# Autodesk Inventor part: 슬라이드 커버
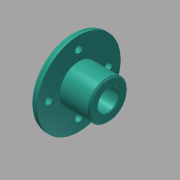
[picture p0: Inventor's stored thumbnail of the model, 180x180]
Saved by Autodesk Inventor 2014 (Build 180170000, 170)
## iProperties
Created: 2015-12
Part Number: 슬라이드 커버
Document SubType Name: Modeling
Designer: mdu
Density: 2.71 g/cm^3
Material: 알루미늄 6061
Mass: 49.5723 g
Surface Area: 80.7135 cm^2
Volume: 18.2924 cm^3
Appearance: 알루미늄 - 평지
Author: mdu
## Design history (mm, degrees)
sketch "스케치1"
  geometry: L1 (-12.5, 0)-(12.5, 0); L2 (-12.5, 0)-(-12.5, 28); L3 (-12.5, 28)-(-7.5, 28); L4 (-7.5, 28)-(-7.5, 13); L5 (-7.5, 13)-(12.5, 13); L6 (12.5, 13)-(12.5, 0); 2 further points
  constraints: 12 end point, 3 perpendicular, 1 coincident, 1 horizontal, 1 midpoint, 1 parallel
  dimensions: "d1" = 56 diameter of L3 L1; "d2" = 26 diameter of L5 L1; "d5" = 5 distance of L2.end L3.end; "d32" = 20 distance of L4.end L5.end
revolve "회전1" sketch "스케치1" stored, may be unused: angle "d6" = 90 deg
sketch "스케치2" dims "d33" = 40
  geometry: 3 further points
  constraints: 2 vertical alignment, 1 coincident, 2 other
hole "구멍1" sketch "스케치2" at (0, 20) diameter "d8" = 5; stored, may be unused: countersink angle "d12" = 90 deg, drill point angle "d14" = 118 deg; dims "d9" = 6, "d10" = 8, "d11" = 4.4, "d13" = 8
hole "구멍2" diameter "d20" = 14; stored, may be unused: countersink angle "d24" = 90 deg, drill point angle "d26" = 0 deg; dims "d18" = 10, "d19" = 10, "d21" = 6, "d22" = 8, "d23" = 4.4, "d25" = 8
fillet "모깎기1" dims "d27" = 3
chamfer "모따기1" distance "d29" = 1; stored, may be unused: second distance "d30" = 2, angle "d31" = 45 deg
chamfer "모따기2" distance "d35" = 0.5; stored, may be unused: second distance "d36" = 2, angle "d37" = 45 deg
node "솔리드1"
pattern_circular "원형 패턴1" dims angle "d16" = 360 deg
